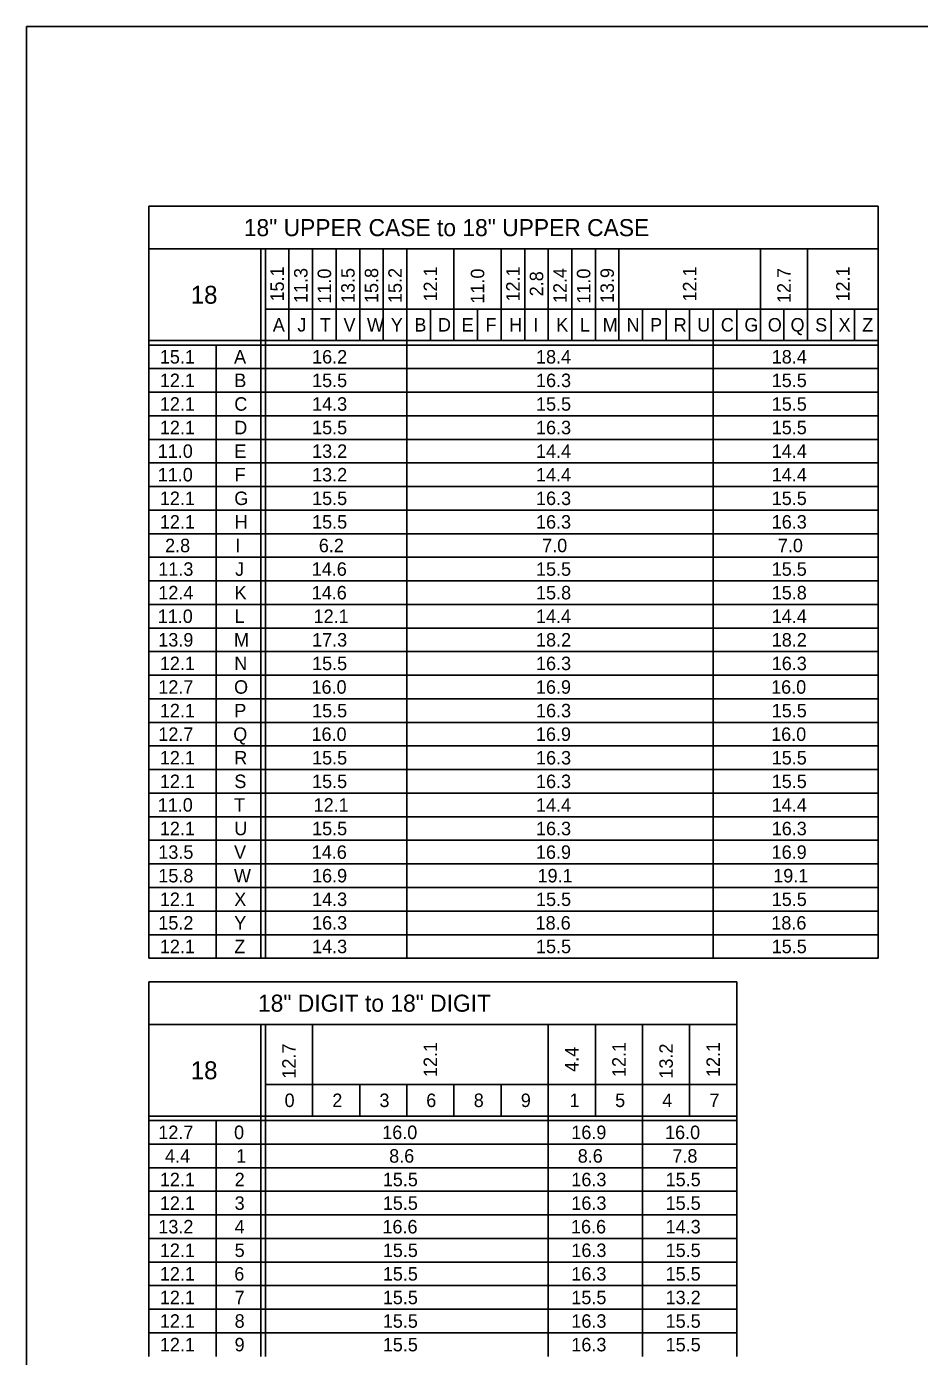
# Model space of a CAD drawing. Extents: x 638421 to 641849, y 297270 to 299646.
# Drawn here: x 640143.3 to 640342.2, y 298146.6 to 298442.6 of the extents above; entities that cross this region are included whole.
import ezdxf

# ---------------------------------------------------------------- set-up
doc = ezdxf.new("R2010")
doc.units = 0
doc.layers.add('1', color=7, linetype='Continuous')
doc.layers.add('2', color=7, linetype='Continuous')

msp = doc.modelspace()

# ---------------------------------------------------------------- linework, layer by layer
at = {"layer": '1'}
for q in [(640929.31, 298442.63), (640143.31, 297878.63)]:
    msp.add_line((640143.31, 298442.63), q, dxfattribs=at)
at = {"layer": '2'}
for p, q in [((640333.01, 298402.63), (640170.51, 298402.63)), ((640170.51, 298402.63), (640170.51, 298235.25)), ((640333.01, 298402.63), (640333.01, 298235.25)), ((640170.51, 298393.13), (640333.01, 298393.13)), ((640195.51, 298393.13), (640195.51, 298235.25)), ((640196.51, 298393.13), (640196.51, 298235.25)), ((640201.76, 298393.13), (640201.76, 298372.75)), ((640207.01, 298393.13), (640207.01, 298372.75)), ((640212.26, 298393.13), (640212.26, 298372.75)), ((640217.51, 298393.13), (640217.51, 298372.75)), ((640222.76, 298393.13), (640222.76, 298372.75)), ((640228.01, 298393.13), (640228.01, 298235.25)), ((640238.51, 298393.13), (640238.51, 298372.75)), ((640249.01, 298393.13), (640249.01, 298372.75)), ((640254.26, 298393.13), (640254.26, 298372.75)), ((640259.51, 298393.13), (640259.51, 298372.75)), ((640264.76, 298393.13), (640264.76, 298372.75)), ((640270.01, 298393.13), (640270.01, 298372.75)), ((640275.26, 298393.13), (640275.26, 298372.75)), ((640306.76, 298393.13), (640306.76, 298372.75)), ((640317.26, 298393.13), (640317.26, 298372.75)), ((640196.51, 298379.75), (640333.01, 298379.75)), ((640233.26, 298379.75), (640233.26, 298372.75)), ((640243.76, 298379.75), (640243.76, 298372.75)), ((640280.51, 298379.75), (640280.51, 298372.75)), ((640285.76, 298379.75), (640285.76, 298372.75)), ((640291.01, 298379.75), (640291.01, 298372.75)), ((640291.01, 298379.75), (640291.01, 298372.75)), ((640296.26, 298379.75), (640296.26, 298235.25)), ((640301.51, 298379.75), (640301.51, 298372.75)), ((640312.01, 298379.75), (640312.01, 298372.75)), ((640322.51, 298379.75), (640322.51, 298372.75)), ((640327.76, 298379.75), (640327.76, 298372.75)), ((640333.01, 298372.75), (640170.51, 298372.75)), ((640333.01, 298371.75), (640170.51, 298371.75)), ((640185.51, 298371.75), (640185.51, 298235.25)), ((640333.01, 298366.5), (640170.51, 298366.5)), ((640333.01, 298361.25), (640170.51, 298361.25)), ((640333.01, 298356), (640170.51, 298356)), ((640333.01, 298350.75), (640170.51, 298350.75)), ((640333.01, 298345.5), (640170.51, 298345.5)), ((640333.01, 298340.25), (640170.51, 298340.25)), ((640333.01, 298335), (640170.51, 298335)), ((640333.01, 298329.75), (640170.51, 298329.75)), ((640333.01, 298324.5), (640170.51, 298324.5)), ((640333.01, 298319.25), (640170.51, 298319.25)), ((640333.01, 298314), (640170.51, 298314)), ((640333.01, 298308.75), (640170.51, 298308.75)), ((640333.01, 298303.5), (640170.51, 298303.5)), ((640333.01, 298298.25), (640170.51, 298298.25)), ((640333.01, 298293), (640170.51, 298293)), ((640333.01, 298287.75), (640170.51, 298287.75)), ((640333.01, 298282.5), (640170.51, 298282.5)), ((640333.01, 298277.25), (640170.51, 298277.25)), ((640333.01, 298272), (640170.51, 298272)), ((640333.01, 298266.75), (640170.51, 298266.75)), ((640333.01, 298261.5), (640170.51, 298261.5)), ((640333.01, 298256.25), (640170.51, 298256.25)), ((640333.01, 298251), (640170.51, 298251)), ((640333.01, 298245.75), (640170.51, 298245.75)), ((640333.01, 298240.5), (640170.51, 298240.5)), ((640170.51, 298235.25), (640170.51, 298235.25)), ((640170.51, 298235.25), (640333.01, 298235.25)), ((640301.51, 298230), (640170.51, 298230)), ((640170.51, 298230), (640170.51, 298146.63)), ((640301.51, 298146.63), (640301.51, 298230)), ((640170.51, 298220.5), (640301.51, 298220.5)), ((640195.51, 298220.5), (640195.51, 298146.63)), ((640196.51, 298220.5), (640196.51, 298146.63)), ((640207.01, 298220.5), (640207.01, 298200.13)), ((640259.51, 298220.5), (640259.51, 298146.63)), ((640270.01, 298220.5), (640270.01, 298200.13)), ((640280.51, 298220.5), (640280.51, 298146.63)), ((640291.01, 298220.5), (640291.01, 298200.13)), ((640196.51, 298207.13), (640301.51, 298207.13)), ((640217.51, 298207.13), (640217.51, 298200.13)), ((640228.01, 298207.13), (640228.01, 298200.13)), ((640238.51, 298207.13), (640238.51, 298200.13)), ((640249.01, 298207.13), (640249.01, 298200.13)), ((640301.51, 298200.13), (640170.51, 298200.13)), ((640301.51, 298199.13), (640170.51, 298199.13)), ((640185.51, 298199.13), (640185.51, 298146.63)), ((640301.51, 298193.88), (640170.51, 298193.88)), ((640301.51, 298188.63), (640170.51, 298188.63)), ((640301.51, 298183.38), (640170.51, 298183.38)), ((640301.51, 298178.13), (640170.51, 298178.13)), ((640301.51, 298172.88), (640170.51, 298172.88)), ((640301.51, 298167.63), (640170.51, 298167.63)), ((640301.51, 298162.38), (640170.51, 298162.38)), ((640301.51, 298157.13), (640170.51, 298157.13)), ((640301.51, 298151.88), (640170.51, 298151.88))]:
    msp.add_line(p, q, dxfattribs=at)

# ---------------------------------------------------------------- texts
for s, height, p in [('18" UPPER CASE to 18" UPPER CASE', 3.8, (640191.7, 298395.98)), ('18', 4, (640179.88, 298380.94)), ('A', 3, (640198.16, 298374.75)), ('J', 3, (640203.64, 298374.75)), ('T', 3, (640208.64, 298374.75)), ('V', 3, (640213.91, 298374.75)), ('W', 3, (640219.13, 298374.75)), ('Y', 3, (640224.44, 298374.75)), ('B', 3, (640229.7, 298374.75)), ('D', 3, (640234.95, 298374.75)), ('E', 3, (640240.22, 298374.75)), ('F', 3, (640245.52, 298374.75)), ('H', 3, (640250.79, 298374.75)), ('I', 3, (640256.2, 298374.75)), ('K', 3, (640261.29, 298374.75)), ('L', 3, (640266.54, 298374.75)), ('M', 3, (640271.63, 298374.75)), ('N', 3, (640276.95, 298374.75)), ('P', 3, (640282.2, 298374.75)), ('R', 3, (640287.45, 298374.75)), ('U', 3, (640292.69, 298374.75)), ('C', 3, (640297.95, 298374.75)), ('G', 3, (640303.2, 298374.75)), ('O', 3, (640308.41, 298374.75)), ('Q', 3, (640313.48, 298374.75)), ('S', 3, (640318.97, 298374.75)), ('X', 3, (640324.19, 298374.75)), ('Z', 3, (640329.45, 298374.75)), ('15.1', 3, (640173, 298367.63)), ('A', 3, (640189.53, 298367.63)), ('16.2', 3, (640206.91, 298367.63)), ('18.4', 3, (640256.79, 298367.63)), ('18.4', 3, (640309.29, 298367.63)), ('12.1', 3, (640173, 298362.38)), ('B', 3, (640189.58, 298362.38)), ('15.5', 3, (640206.91, 298362.38)), ('16.3', 3, (640256.79, 298362.38)), ('15.5', 3, (640309.29, 298362.38)), ('12.1', 3, (640173, 298357.13)), ('C', 3, (640189.58, 298357.13)), ('14.3', 3, (640206.91, 298357.13)), ('15.5', 3, (640256.79, 298357.13)), ('15.5', 3, (640309.29, 298357.13)), ('12.1', 3, (640173, 298351.88)), ('D', 3, (640189.58, 298351.88)), ('15.5', 3, (640206.91, 298351.88)), ('16.3', 3, (640256.79, 298351.88)), ('15.5', 3, (640309.29, 298351.88)), ('11.0', 3, (640172.53, 298346.63)), ('E', 3, (640189.59, 298346.63)), ('13.2', 3, (640206.91, 298346.63)), ('14.4', 3, (640256.79, 298346.63)), ('14.4', 3, (640309.29, 298346.63)), ('11.0', 3, (640172.53, 298341.38)), ('13.2', 3, (640206.91, 298341.38)), ('F', 3, (640189.65, 298341.38)), ('14.4', 3, (640256.79, 298341.38)), ('14.4', 3, (640309.29, 298341.38)), ('12.1', 3, (640173, 298336.13)), ('G', 3, (640189.58, 298336.13)), ('15.5', 3, (640206.91, 298336.13)), ('16.3', 3, (640256.79, 298336.13)), ('15.5', 3, (640309.29, 298336.13)), ('12.1', 3, (640173, 298330.88)), ('H', 3, (640189.66, 298330.88)), ('15.5', 3, (640206.91, 298330.88)), ('16.3', 3, (640256.79, 298330.88)), ('16.3', 3, (640309.29, 298330.88)), ('2.8', 3, (640174.16, 298325.63)), ('I', 3, (640189.83, 298325.63)), ('6.2', 3, (640208.41, 298325.63)), ('7.0', 3, (640258.16, 298325.63)), ('7.0', 3, (640310.66, 298325.63)), ('11.3', 3, (640172.66, 298320.38)), ('J', 3, (640189.77, 298320.38)), ('14.6', 3, (640206.83, 298320.38)), ('15.5', 3, (640256.79, 298320.38)), ('15.5', 3, (640309.29, 298320.38)), ('12.4', 3, (640172.66, 298315.13)), ('K', 3, (640189.66, 298315.13)), ('14.6', 3, (640206.83, 298315.13)), ('15.8', 3, (640256.79, 298315.13)), ('15.8', 3, (640309.29, 298315.13)), ('11.0', 3, (640172.53, 298309.88)), ('L', 3, (640189.66, 298309.88)), ('12.1', 3, (640207.25, 298309.88)), ('14.4', 3, (640256.79, 298309.88)), ('14.4', 3, (640309.29, 298309.88)), ('13.9', 3, (640172.65, 298304.63)), ('M', 3, (640189.51, 298304.63)), ('17.3', 3, (640206.91, 298304.63)), ('18.2', 3, (640256.79, 298304.63)), ('18.2', 3, (640309.29, 298304.63)), ('12.1', 3, (640173, 298299.38)), ('N', 3, (640189.58, 298299.38)), ('15.5', 3, (640206.91, 298299.38)), ('16.3', 3, (640256.79, 298299.38)), ('16.3', 3, (640309.29, 298299.38)), ('12.7', 3, (640172.66, 298294.13)), ('O', 3, (640189.53, 298294.13)), ('16.0', 3, (640206.78, 298294.13)), ('16.9', 3, (640256.77, 298294.13)), ('16.0', 3, (640309.16, 298294.13)), ('12.1', 3, (640173, 298288.88)), ('P', 3, (640189.58, 298288.88)), ('15.5', 3, (640206.91, 298288.88)), ('16.3', 3, (640256.79, 298288.88)), ('15.5', 3, (640309.29, 298288.88)), ('12.7', 3, (640172.66, 298283.63)), ('Q', 3, (640189.35, 298283.63)), ('16.0', 3, (640206.78, 298283.63)), ('16.9', 3, (640256.77, 298283.63)), ('16.0', 3, (640309.16, 298283.63)), ('12.1', 3, (640173, 298278.38)), ('R', 3, (640189.58, 298278.38)), ('15.5', 3, (640206.91, 298278.38)), ('16.3', 3, (640256.79, 298278.38)), ('15.5', 3, (640309.29, 298278.38)), ('12.1', 3, (640173, 298273.13)), ('S', 3, (640189.59, 298273.13)), ('15.5', 3, (640206.91, 298273.13)), ('16.3', 3, (640256.79, 298273.13)), ('15.5', 3, (640309.29, 298273.13)), ('11.0', 3, (640172.53, 298267.88)), ('T', 3, (640189.52, 298267.88)), ('12.1', 3, (640207.25, 298267.88)), ('14.4', 3, (640256.79, 298267.88)), ('14.4', 3, (640309.29, 298267.88)), ('12.1', 3, (640173, 298262.63)), ('U', 3, (640189.57, 298262.63)), ('15.5', 3, (640206.91, 298262.63)), ('16.3', 3, (640256.79, 298262.63)), ('16.3', 3, (640309.29, 298262.63)), ('13.5', 3, (640172.66, 298257.38)), ('V', 3, (640189.53, 298257.38)), ('14.6', 3, (640206.83, 298257.38)), ('16.9', 3, (640256.77, 298257.38)), ('16.9', 3, (640309.27, 298257.38)), ('15.8', 3, (640172.66, 298252.13)), ('W', 3, (640189.51, 298252.13)), ('16.9', 3, (640206.9, 298252.13)), ('19.1', 3, (640257.13, 298252.13)), ('19.1', 3, (640309.63, 298252.13)), ('12.1', 3, (640173, 298246.88)), ('X', 3, (640189.57, 298246.88)), ('14.3', 3, (640206.91, 298246.88)), ('15.5', 3, (640256.79, 298246.88)), ('15.5', 3, (640309.29, 298246.88)), ('15.2', 3, (640172.66, 298241.63)), ('Y', 3, (640189.57, 298241.63)), ('16.3', 3, (640206.91, 298241.63)), ('18.6', 3, (640256.7, 298241.63)), ('18.6', 3, (640309.2, 298241.63)), ('12.1', 3, (640173, 298236.38)), ('Z', 3, (640189.58, 298236.38)), ('14.3', 3, (640206.91, 298236.38)), ('15.5', 3, (640256.79, 298236.38)), ('15.5', 3, (640309.29, 298236.38)), ('18" DIGIT to 18" DIGIT', 3.8, (640194.86, 298223.35)), ('18', 4, (640179.88, 298208.31)), ('0', 3, (640200.78, 298202.13)), ('2', 3, (640211.41, 298202.13)), ('3', 3, (640221.91, 298202.13)), ('6', 3, (640232.33, 298202.13)), ('8', 3, (640242.91, 298202.13)), ('9', 3, (640253.4, 298202.13)), ('1', 3, (640264.25, 298202.13)), ('5', 3, (640274.41, 298202.13)), ('4', 3, (640284.91, 298202.13)), ('7', 3, (640295.41, 298202.13)), ('12.7', 3, (640172.66, 298195)), ('0', 3, (640189.53, 298195)), ('16.0', 3, (640222.53, 298195)), ('16.9', 3, (640264.65, 298195)), ('16.0', 3, (640285.53, 298195)), ('4.4', 3, (640174.16, 298189.75)), ('1', 3, (640190, 298189.75)), ('8.6', 3, (640224.08, 298189.75)), ('8.6', 3, (640266.08, 298189.75)), ('7.8', 3, (640287.16, 298189.75)), ('12.1', 3, (640173, 298184.5)), ('2', 3, (640189.66, 298184.5)), ('16.3', 3, (640264.66, 298184.5)), ('15.5', 3, (640222.66, 298184.5)), ('15.5', 3, (640285.66, 298184.5)), ('12.1', 3, (640173, 298179.25)), ('3', 3, (640189.66, 298179.25)), ('15.5', 3, (640222.66, 298179.25)), ('16.3', 3, (640264.66, 298179.25)), ('15.5', 3, (640285.66, 298179.25)), ('13.2', 3, (640172.66, 298174)), ('4', 3, (640189.66, 298174)), ('16.6', 3, (640222.58, 298174)), ('16.6', 3, (640264.58, 298174)), ('14.3', 3, (640285.66, 298174)), ('12.1', 3, (640173, 298168.75)), ('5', 3, (640189.66, 298168.75)), ('15.5', 3, (640222.66, 298168.75)), ('16.3', 3, (640264.66, 298168.75)), ('15.5', 3, (640285.66, 298168.75)), ('12.1', 3, (640173, 298163.5)), ('6', 3, (640189.58, 298163.5)), ('15.5', 3, (640222.66, 298163.5)), ('16.3', 3, (640264.66, 298163.5)), ('15.5', 3, (640285.66, 298163.5)), ('12.1', 3, (640173, 298158.25)), ('7', 3, (640189.66, 298158.25)), ('15.5', 3, (640222.66, 298158.25)), ('15.5', 3, (640264.66, 298158.25)), ('13.2', 3, (640285.66, 298158.25)), ('12.1', 3, (640173, 298153)), ('8', 3, (640189.66, 298153)), ('15.5', 3, (640222.66, 298153)), ('16.3', 3, (640264.66, 298153)), ('15.5', 3, (640285.66, 298153)), ('12.1', 3, (640173, 298147.75)), ('9', 3, (640189.65, 298147.75)), ('15.5', 3, (640222.66, 298147.75)), ('16.3', 3, (640264.66, 298147.75)), ('15.5', 3, (640285.66, 298147.75))]:
    msp.add_text(s, height=height, dxfattribs=at).set_placement(p)
for s, p in [('15.1', (640200.64, 298381.43)), ('12.1', (640234.76, 298381.43)), ('12.1', (640253.14, 298381.43)), ('12.1', (640292.51, 298381.43)), ('12.1', (640326.64, 298381.43)), ('11.3', (640205.89, 298381.09)), ('11.0', (640211.14, 298380.96)), ('13.5', (640216.39, 298381.09)), ('15.8', (640221.64, 298381.09)), ('15.2', (640226.89, 298381.09)), ('11.0', (640245.26, 298380.96)), ('2.8', (640258.39, 298382.59)), ('12.4', (640263.64, 298381.09)), ('11.0', (640268.89, 298380.96)), ('13.9', (640274.14, 298381.08)), ('12.7', (640313.51, 298381.09)), ('12.7', (640203.26, 298208.46)), ('12.1', (640234.76, 298208.81)), ('4.4', (640266.26, 298209.96)), ('12.1', (640276.76, 298208.81)), ('13.2', (640287.26, 298208.46)), ('12.1', (640297.76, 298208.81))]:
    msp.add_text(s, height=3, rotation=90, dxfattribs=at).set_placement(p)

doc.saveas('drawing.dxf')
